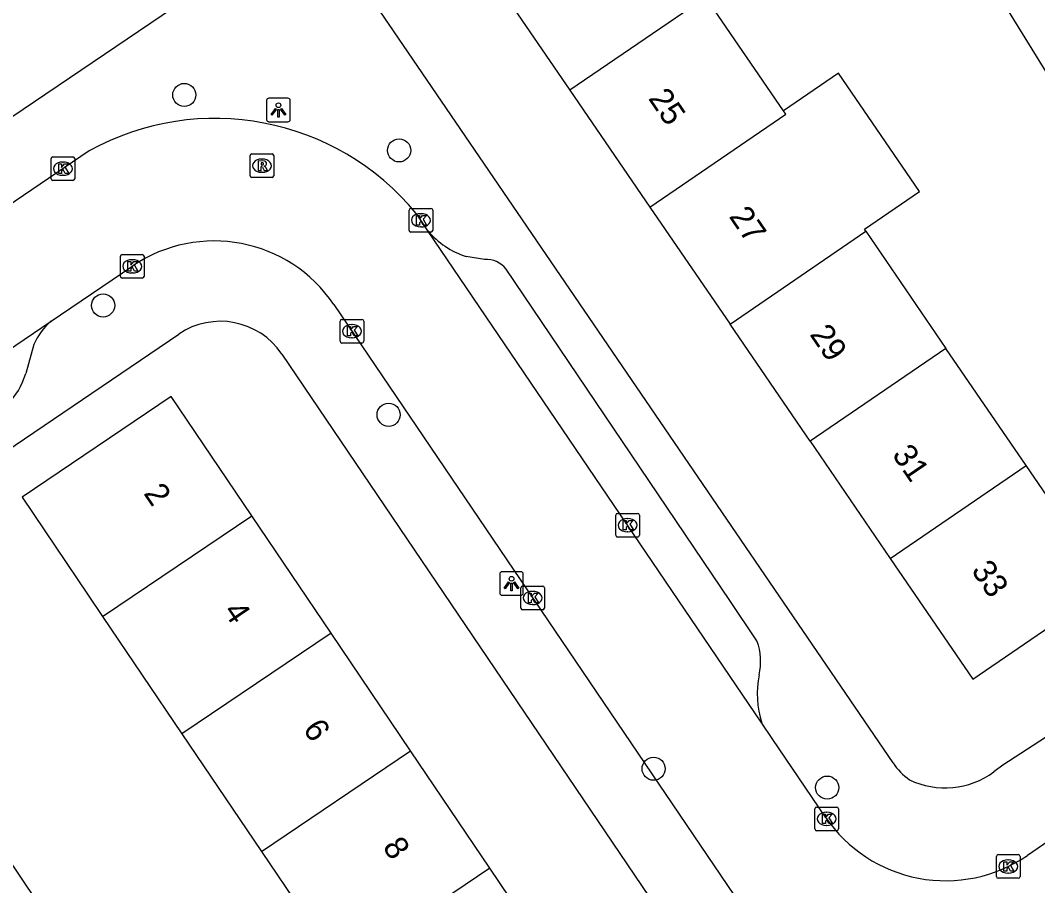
# Model space of a CAD drawing. Extents: x 160037 to 160839, y 385326 to 386441.
# Drawn here: x 160156.36 to 160199.4, y 386005.05 to 386041.67 of the extents above; entities that cross this region are included whole.
import ezdxf

# ---------------------------------------------------------------- set-up
doc = ezdxf.new("R2010")
doc.units = 0
for name, color, linetype in [('IMGEO_Boom', 7, 'Continuous'), ('IMGEO_Kolk', 7, 'Continuous'), ('IMGEO_Lichtpunt', 7, 'Continuous'), ('IMGEO_Pand', 7, 'Continuous'), ('IMGEO_Pand_nummerreeks', 7, 'Continuous'), ('IMGEO_Rijbaan_lokaal_open', 7, 'Continuous'), ('IMGEO_Rioolput', 7, 'Continuous'), ('IMGEO_Voetpad_open', 7, 'Continuous')]:
    doc.layers.add(name, color=color, linetype=linetype)

msp = doc.modelspace()

# ---------------------------------------------------------------- linework, layer by layer
at = {"layer": 'IMGEO_Boom'}
for centre in [(160163.294, 386038.508), (160172.383, 386036.165), (160159.86, 386029.602), (160171.938, 386024.977), (160183.15, 386010), (160190.492, 386009.202)]:
    msp.add_circle(centre, 0.489, dxfattribs=at)
at = {"layer": 'IMGEO_Kolk'}
for p, q in [((160157.657, 386034.965), (160157.657, 386035.817)), ((160157.732, 386035.891), (160158.584, 386035.891)), ((160158.658, 386035.817), (160158.658, 386034.965)), ((160158.145, 386035.671), (160158.17, 386035.671)), ((160158.168, 386035.111), (160158.143, 386035.111)), ((160158.584, 386034.891), (160157.732, 386034.891)), ((160172.8, 386032.78), (160172.8, 386033.632)), ((160172.875, 386033.706), (160173.727, 386033.706)), ((160173.801, 386033.632), (160173.801, 386032.78)), ((160173.288, 386033.486), (160173.313, 386033.486)), ((160173.311, 386032.926), (160173.286, 386032.926)), ((160173.727, 386032.706), (160172.875, 386032.706)), ((160160.589, 386030.832), (160160.589, 386031.684)), ((160160.664, 386031.758), (160161.516, 386031.758)), ((160161.077, 386031.538), (160161.102, 386031.538)), ((160161.59, 386031.684), (160161.59, 386030.832)), ((160161.516, 386030.758), (160160.664, 386030.758)), ((160161.1, 386030.978), (160161.075, 386030.978)), ((160169.883, 386028.088), (160169.883, 386028.94)), ((160169.958, 386029.014), (160170.81, 386029.014)), ((160170.884, 386028.94), (160170.884, 386028.088)), ((160170.371, 386028.794), (160170.396, 386028.794)), ((160170.394, 386028.234), (160170.369, 386028.234)), ((160170.81, 386028.014), (160169.958, 386028.014)), ((160181.546, 386019.879), (160181.546, 386020.731)), ((160181.621, 386020.805), (160182.473, 386020.805)), ((160182.547, 386020.731), (160182.547, 386019.879)), ((160182.034, 386020.585), (160182.059, 386020.585)), ((160182.057, 386020.025), (160182.032, 386020.025)), ((160182.473, 386019.805), (160181.621, 386019.805)), ((160177.604, 386017.727), (160178.456, 386017.727)), ((160177.529, 386016.801), (160177.529, 386017.653)), ((160178.017, 386017.507), (160178.042, 386017.507)), ((160178.53, 386017.653), (160178.53, 386016.801)), ((160178.04, 386016.947), (160178.015, 386016.947)), ((160178.456, 386016.727), (160177.604, 386016.727)), ((160189.97, 386007.453), (160189.97, 386008.305)), ((160190.045, 386008.379), (160190.897, 386008.379)), ((160190.971, 386008.305), (160190.971, 386007.453)), ((160190.458, 386008.159), (160190.483, 386008.159)), ((160190.897, 386007.379), (160190.045, 386007.379)), ((160190.481, 386007.599), (160190.456, 386007.599)), ((160197.649, 386005.44), (160197.649, 386006.292)), ((160197.724, 386006.366), (160198.576, 386006.366)), ((160198.137, 386006.146), (160198.162, 386006.146)), ((160198.65, 386006.292), (160198.65, 386005.44)), ((160198.576, 386005.366), (160197.724, 386005.366)), ((160198.16, 386005.586), (160198.135, 386005.586))]:
    msp.add_line(p, q, dxfattribs=at)
for points in [[(160157.657, 386034.965), (160157.657, 386035.817)], [(160157.732, 386035.891), (160158.584, 386035.891)], [(160158.658, 386035.817), (160158.658, 386034.965)], [(160157.978, 386035.591), (160158.101, 386035.591), (160158.101, 386035.44), (160158.231, 386035.591), (160158.395, 386035.591), (160158.249, 386035.44), (160158.402, 386035.191), (160158.25, 386035.191), (160158.165, 386035.355), (160158.101, 386035.288), (160158.101, 386035.191), (160157.978, 386035.191), (160157.978, 386035.591)], [(160158.584, 386034.891), (160157.732, 386034.891)], [(160172.8, 386032.78), (160172.8, 386033.632)], [(160172.875, 386033.706), (160173.727, 386033.706)], [(160173.801, 386033.632), (160173.801, 386032.78)], [(160173.121, 386033.406), (160173.244, 386033.406), (160173.244, 386033.255), (160173.374, 386033.406), (160173.538, 386033.406), (160173.392, 386033.255), (160173.545, 386033.006), (160173.393, 386033.006), (160173.308, 386033.17), (160173.244, 386033.103), (160173.244, 386033.006), (160173.121, 386033.006), (160173.121, 386033.406)], [(160173.727, 386032.706), (160172.875, 386032.706)], [(160160.589, 386030.832), (160160.589, 386031.684)], [(160160.664, 386031.758), (160161.516, 386031.758)], [(160161.59, 386031.684), (160161.59, 386030.832)], [(160160.91, 386031.458), (160161.033, 386031.458), (160161.033, 386031.307), (160161.163, 386031.458), (160161.327, 386031.458), (160161.181, 386031.307), (160161.334, 386031.058), (160161.182, 386031.058), (160161.097, 386031.222), (160161.033, 386031.155), (160161.033, 386031.058), (160160.91, 386031.058), (160160.91, 386031.458)], [(160161.516, 386030.758), (160160.664, 386030.758)], [(160169.883, 386028.088), (160169.883, 386028.94)], [(160169.958, 386029.014), (160170.81, 386029.014)], [(160170.884, 386028.94), (160170.884, 386028.088)], [(160170.204, 386028.714), (160170.327, 386028.714), (160170.327, 386028.563), (160170.457, 386028.714), (160170.621, 386028.714), (160170.475, 386028.563), (160170.628, 386028.314), (160170.476, 386028.314), (160170.391, 386028.478), (160170.327, 386028.411), (160170.327, 386028.314), (160170.204, 386028.314), (160170.204, 386028.714)], [(160170.81, 386028.014), (160169.958, 386028.014)], [(160181.546, 386019.879), (160181.546, 386020.731)], [(160181.621, 386020.805), (160182.473, 386020.805)], [(160182.547, 386020.731), (160182.547, 386019.879)], [(160181.867, 386020.505), (160181.99, 386020.505), (160181.99, 386020.354), (160182.12, 386020.505), (160182.284, 386020.505), (160182.138, 386020.354), (160182.291, 386020.105), (160182.139, 386020.105), (160182.054, 386020.269), (160181.99, 386020.202), (160181.99, 386020.105), (160181.867, 386020.105), (160181.867, 386020.505)], [(160182.473, 386019.805), (160181.621, 386019.805)], [(160177.604, 386017.727), (160178.456, 386017.727)], [(160177.529, 386016.801), (160177.529, 386017.653)], [(160177.85, 386017.427), (160177.973, 386017.427), (160177.973, 386017.276), (160178.103, 386017.427), (160178.267, 386017.427), (160178.121, 386017.276), (160178.274, 386017.027), (160178.122, 386017.027), (160178.037, 386017.191), (160177.973, 386017.124), (160177.973, 386017.027), (160177.85, 386017.027), (160177.85, 386017.427)], [(160178.53, 386017.653), (160178.53, 386016.801)], [(160178.456, 386016.727), (160177.604, 386016.727)], [(160189.97, 386007.453), (160189.97, 386008.305)], [(160190.045, 386008.379), (160190.897, 386008.379)], [(160190.971, 386008.305), (160190.971, 386007.453)], [(160190.291, 386008.079), (160190.414, 386008.079), (160190.414, 386007.928), (160190.544, 386008.079), (160190.708, 386008.079), (160190.562, 386007.928), (160190.715, 386007.679), (160190.563, 386007.679), (160190.478, 386007.843), (160190.414, 386007.776), (160190.414, 386007.679), (160190.291, 386007.679), (160190.291, 386008.079)], [(160190.897, 386007.379), (160190.045, 386007.379)], [(160197.649, 386005.44), (160197.649, 386006.292)], [(160197.724, 386006.366), (160198.576, 386006.366)], [(160198.65, 386006.292), (160198.65, 386005.44)], [(160197.97, 386006.066), (160198.093, 386006.066), (160198.093, 386005.915), (160198.223, 386006.066), (160198.387, 386006.066), (160198.241, 386005.915), (160198.394, 386005.666), (160198.242, 386005.666), (160198.157, 386005.83), (160198.093, 386005.763), (160198.093, 386005.666), (160197.97, 386005.666), (160197.97, 386006.066)], [(160198.576, 386005.366), (160197.724, 386005.366)]]:
    msp.add_lwpolyline(points, dxfattribs=at)
for centre, start, end in [((160157.734, 386035.815), 91.552, 178.448), ((160157.734, 386035.815), 91.552, 178.448), ((160158.582, 386035.815), 1.552, 88.448), ((160158.582, 386035.815), 1.552, 88.448), ((160157.734, 386034.967), 181.552, 268.448), ((160157.734, 386034.967), 181.552, 268.448), ((160158.582, 386034.967), 271.552, 358.448), ((160158.582, 386034.967), 271.552, 358.448), ((160172.877, 386033.63), 91.552, 178.448), ((160172.877, 386033.63), 91.552, 178.448), ((160173.725, 386033.63), 1.552, 88.448), ((160173.725, 386033.63), 1.552, 88.448), ((160172.877, 386032.782), 181.552, 268.448), ((160172.877, 386032.782), 181.552, 268.448), ((160173.725, 386032.782), 271.552, 358.448), ((160173.725, 386032.782), 271.552, 358.448), ((160160.666, 386031.682), 91.552, 178.448), ((160160.666, 386031.682), 91.552, 178.448), ((160161.514, 386031.682), 1.552, 88.448), ((160161.514, 386031.682), 1.552, 88.448), ((160160.666, 386030.834), 181.552, 268.448), ((160160.666, 386030.834), 181.552, 268.448), ((160161.514, 386030.834), 271.552, 358.448), ((160161.514, 386030.834), 271.552, 358.448), ((160169.96, 386028.938), 91.552, 178.448), ((160169.96, 386028.938), 91.552, 178.448), ((160170.808, 386028.938), 1.552, 88.448), ((160170.808, 386028.938), 1.552, 88.448), ((160169.96, 386028.09), 181.552, 268.448), ((160169.96, 386028.09), 181.552, 268.448), ((160170.808, 386028.09), 271.552, 358.448), ((160170.808, 386028.09), 271.552, 358.448), ((160181.623, 386020.729), 91.552, 178.448), ((160181.623, 386020.729), 91.552, 178.448), ((160182.471, 386020.729), 1.552, 88.448), ((160182.471, 386020.729), 1.552, 88.448), ((160181.623, 386019.881), 181.552, 268.448), ((160181.623, 386019.881), 181.552, 268.448), ((160182.471, 386019.881), 271.552, 358.448), ((160182.471, 386019.881), 271.552, 358.448), ((160177.606, 386017.651), 91.552, 178.448), ((160177.606, 386017.651), 91.552, 178.448), ((160178.454, 386017.651), 1.552, 88.448), ((160178.454, 386017.651), 1.552, 88.448), ((160177.606, 386016.803), 181.552, 268.448), ((160177.606, 386016.803), 181.552, 268.448), ((160178.454, 386016.803), 271.552, 358.448), ((160178.454, 386016.803), 271.552, 358.448), ((160190.047, 386008.303), 91.552, 178.448), ((160190.047, 386008.303), 91.552, 178.448), ((160190.895, 386008.303), 1.552, 88.448), ((160190.895, 386008.303), 1.552, 88.448), ((160190.047, 386007.455), 181.552, 268.448), ((160190.047, 386007.455), 181.552, 268.448), ((160190.895, 386007.455), 271.552, 358.448), ((160190.895, 386007.455), 271.552, 358.448), ((160197.726, 386006.29), 91.552, 178.448), ((160197.726, 386006.29), 91.552, 178.448), ((160198.574, 386006.29), 1.552, 88.448), ((160198.574, 386006.29), 1.552, 88.448), ((160197.726, 386005.442), 181.552, 268.448), ((160197.726, 386005.442), 181.552, 268.448), ((160198.574, 386005.442), 271.552, 358.448), ((160198.574, 386005.442), 271.552, 358.448)]:
    msp.add_arc(centre, 0.0765, start, end, dxfattribs=at)
for centre, major_axis, ratio, start_param, end_param in [((160158.144, 386035.391), (-0.387, 0.002), 0.722429, 4.712389, 7.853982), ((160158.169, 386035.391), (-0.39, 0.002), 0.717154, 1.570796, 4.712389), ((160173.287, 386033.206), (-0.387, 0.002), 0.722429, 4.712389, 7.853982), ((160173.312, 386033.206), (-0.39, 0.002), 0.717154, 1.570796, 4.712389), ((160161.076, 386031.258), (-0.387, 0.002), 0.722429, 4.712389, 7.853982), ((160161.101, 386031.258), (-0.39, 0.002), 0.717154, 1.570796, 4.712389), ((160170.37, 386028.514), (-0.387, 0.002), 0.722429, 4.712389, 7.853982), ((160170.395, 386028.514), (-0.39, 0.002), 0.717154, 1.570796, 4.712389), ((160182.033, 386020.305), (-0.387, 0.002), 0.722429, 4.712389, 7.853982), ((160182.058, 386020.305), (-0.39, 0.002), 0.717154, 1.570796, 4.712389), ((160178.016, 386017.227), (-0.387, 0.002), 0.722429, 4.712389, 7.853982), ((160178.041, 386017.227), (-0.39, 0.002), 0.717154, 1.570796, 4.712389), ((160190.457, 386007.879), (-0.387, 0.002), 0.722429, 4.712389, 7.853982), ((160190.482, 386007.879), (-0.39, 0.002), 0.717154, 1.570796, 4.712389), ((160198.136, 386005.866), (-0.387, 0.002), 0.722429, 4.712389, 7.853982), ((160198.161, 386005.866), (-0.39, 0.002), 0.717154, 1.570796, 4.712389)]:
    msp.add_ellipse(centre, major_axis=major_axis, ratio=ratio, start_param=start_param, end_param=end_param, dxfattribs=at)
at = {"layer": 'IMGEO_Lichtpunt'}
for p, q in [((160167.679, 386038.371), (160166.871, 386038.371)), ((160167.679, 386038.371), (160166.871, 386038.371)), ((160166.777, 386038.276), (160166.777, 386037.469)), ((160166.777, 386038.276), (160166.777, 386037.469)), ((160167.773, 386037.469), (160167.773, 386038.276)), ((160167.773, 386037.469), (160167.773, 386038.276)), ((160166.871, 386037.375), (160167.679, 386037.375)), ((160166.871, 386037.375), (160167.679, 386037.375)), ((160176.637, 386018.24), (160176.637, 386017.433)), ((160176.637, 386018.24), (160176.637, 386017.433)), ((160177.539, 386018.335), (160176.731, 386018.335)), ((160177.539, 386018.335), (160176.731, 386018.335)), ((160177.633, 386017.433), (160177.633, 386018.24)), ((160177.633, 386017.433), (160177.633, 386018.24)), ((160176.731, 386017.339), (160177.539, 386017.339)), ((160176.731, 386017.339), (160177.539, 386017.339))]:
    msp.add_line(p, q, dxfattribs=at)
for points in [[(160167.151, 386037.94), (160167.19, 386037.912), (160167.002, 386037.65), (160166.964, 386037.677), (160167.151, 386037.94)], [(160167.363, 386037.912), (160167.401, 386037.939), (160167.588, 386037.677), (160167.549, 386037.649), (160167.363, 386037.912)], [(160167.253, 386037.892), (160167.3, 386037.892), (160167.3, 386037.57), (160167.253, 386037.57), (160167.253, 386037.892)], [(160177.011, 386017.904), (160177.05, 386017.876), (160176.862, 386017.614), (160176.824, 386017.641), (160177.011, 386017.904)], [(160177.113, 386017.856), (160177.16, 386017.856), (160177.16, 386017.534), (160177.113, 386017.534), (160177.113, 386017.856)], [(160177.223, 386017.876), (160177.261, 386017.903), (160177.448, 386017.641), (160177.409, 386017.613), (160177.223, 386017.876)]]:
    msp.add_lwpolyline(points, dxfattribs=at)
for centre in [(160167.276, 386038.074), (160177.136, 386018.038)]:
    msp.add_circle(centre, 0.0994, dxfattribs=at)
for centre, start, end in [((160166.871, 386038.276), 90, 180), ((160166.871, 386038.276), 90, 180), ((160167.679, 386038.276), 0, 90), ((160167.679, 386038.276), 0, 90), ((160166.871, 386037.469), 180, 270), ((160166.871, 386037.469), 180, 270), ((160167.679, 386037.469), 270, 0), ((160167.679, 386037.469), 270, 360), ((160176.731, 386018.24), 90, 180), ((160176.731, 386018.24), 90, 180), ((160177.539, 386018.24), 0, 90), ((160177.539, 386018.24), 0, 90), ((160176.731, 386017.433), 180, 270), ((160176.731, 386017.433), 180, 270), ((160177.539, 386017.433), 270, 0), ((160177.539, 386017.433), 270, 360)]:
    msp.add_arc(centre, 0.0946, start, end, dxfattribs=at)
at = {"layer": 'IMGEO_Pand'}
for points in [[(160176.217, 386043.664), (160179.604, 386038.712)], [(160202.274, 386040.629), (160199.939, 386039.193), (160197.208, 386043.633)], [(160185.353, 386042.644), (160179.604, 386038.712)], [(160188.638, 386037.843), (160185.353, 386042.644)], [(160192.128, 386032.739), (160192.068, 386032.827), (160194.4, 386034.422), (160190.97, 386039.438), (160188.638, 386037.843)], [(160179.604, 386038.712), (160182.992, 386033.76)], [(160182.992, 386033.76), (160188.741, 386037.692), (160188.638, 386037.843)], [(160182.992, 386033.76), (160186.38, 386028.807)], [(160186.38, 386028.807), (160192.128, 386032.739)], [(160192.128, 386032.739), (160195.516, 386027.788)], [(160189.767, 386023.856), (160186.38, 386028.807)], [(160195.516, 386027.788), (160189.767, 386023.856)], [(160198.903, 386022.835), (160195.516, 386027.788)], [(160166.144, 386020.706), (160162.736, 386025.751), (160156.429, 386021.491), (160159.227, 386017.348), (160159.836, 386016.446)], [(160189.767, 386023.856), (160193.155, 386018.903)], [(160193.155, 386018.903), (160198.903, 386022.835)], [(160193.155, 386018.903), (160196.655, 386013.786), (160202.403, 386017.719), (160198.903, 386022.835)], [(160159.836, 386016.446), (160166.144, 386020.706)], [(160169.502, 386015.734), (160166.144, 386020.706)], [(160159.836, 386016.446), (160163.194, 386011.474)], [(160169.502, 386015.734), (160163.194, 386011.474)], [(160172.86, 386010.762), (160169.502, 386015.734)], [(160163.194, 386011.474), (160166.553, 386006.501)], [(160166.553, 386006.501), (160172.86, 386010.762)], [(160176.218, 386005.79), (160172.86, 386010.762)], [(160155.924, 386000.678), (160158.424, 386002.367), (160155.713, 386006.402)], [(160166.553, 386006.501), (160169.911, 386001.529)], [(160176.218, 386005.79), (160169.911, 386001.529)], [(160179.576, 386000.818), (160176.218, 386005.79)]]:
    msp.add_lwpolyline(points, dxfattribs=at)
at = {"layer": 'IMGEO_Rijbaan_lokaal_open'}
for points in [[(160159.266, 386036.142), (160139.533, 386022.738), (160124.669, 386012.596), (160120.145, 386009.569)], [(160173.603, 386032.759), (160173.237, 386033.299), (160173.106, 386033.492)], [(160187.724, 386011.929), (160173.603, 386032.759)], [(160157.666, 386028.94), (160158.051, 386029.201), (160161.116, 386031.277)], [(160169.622, 386029.641), (160186.862, 386004.189)], [(160128.204, 386009.022), (160129.232, 386009.733), (160151.628, 386024.852), (160157.666, 386028.94)], [(160190.421, 386007.951), (160188.166, 386011.277), (160187.724, 386011.929)], [(160202.396, 386008.684), (160198.96, 386006.332)]]:
    msp.add_lwpolyline(points, dxfattribs=at)
for centre, radius, start, end in [((160164.593, 386026.499), 11.017, 39.4041, 118.917), ((160164.551, 386026.204), 6.126, 34.1267, 124.0993), ((160195.497, 386011.394), 6.133, 214.1483, 304.38)]:
    msp.add_arc(centre, radius, start, end, dxfattribs=at)
at = {"layer": 'IMGEO_Rioolput'}
for p, q in [((160166.077, 386035.09), (160166.077, 386035.942)), ((160166.152, 386036.016), (160167.004, 386036.016)), ((160166.565, 386035.796), (160166.59, 386035.796)), ((160167.078, 386035.942), (160167.078, 386035.09)), ((160167.004, 386035.016), (160166.152, 386035.016)), ((160166.588, 386035.236), (160166.563, 386035.236))]:
    msp.add_line(p, q, dxfattribs=at)
for points in [[(160166.077, 386035.09), (160166.077, 386035.942)], [(160166.152, 386036.016), (160167.004, 386036.016)], [(160167.078, 386035.942), (160167.078, 386035.09)], [(160166.666, 386035.714), (160166.414, 386035.716), (160166.414, 386035.316)], [(160166.414, 386035.316), (160166.538, 386035.316), (160166.538, 386035.478), (160166.549, 386035.478)], [(160166.592, 386035.635), (160166.538, 386035.635), (160166.538, 386035.554)], [(160166.538, 386035.554), (160166.59, 386035.554)], [(160166.596, 386035.449), (160166.667, 386035.316), (160166.807, 386035.316), (160166.742, 386035.442)], [(160167.004, 386035.016), (160166.152, 386035.016)]]:
    msp.add_lwpolyline(points, dxfattribs=at)
for centre, radius, start, end in [((160166.154, 386035.94), 0.0765, 91.552, 178.448), ((160166.154, 386035.94), 0.0765, 91.552, 178.448), ((160167.002, 386035.94), 0.0765, 1.552, 88.448), ((160167.002, 386035.94), 0.0765, 1.552, 88.448), ((160166.548, 386035.425), 0.0533, 26.0293, 88.6989), ((160166.574, 386035.743), 0.19, 274.7715, 282.9687), ((160166.598, 386035.539), 0.0964, 77.0061, 93.1865), ((160166.612, 386035.596), 0.0378, 276.6634, 79.6772), ((160166.665, 386035.604), 0.109, 350.3612, 89.416), ((160166.663, 386035.604), 0.112, 277.5842, 350.9817), ((160166.647, 386035.389), 0.108, 29.5134, 73.7905), ((160166.154, 386035.092), 0.0765, 181.552, 268.448), ((160166.154, 386035.092), 0.0765, 181.552, 268.448), ((160167.002, 386035.092), 0.0765, 271.552, 358.448), ((160167.002, 386035.092), 0.0765, 271.552, 358.448)]:
    msp.add_arc(centre, radius, start, end, dxfattribs=at)
for centre, major_axis, ratio, start_param, end_param in [((160166.564, 386035.516), (-0.387, 0.002), 0.722429, 4.712389, 7.853982), ((160166.589, 386035.516), (-0.39, 0.002), 0.717154, 1.570796, 4.712389)]:
    msp.add_ellipse(centre, major_axis=major_axis, ratio=ratio, start_param=start_param, end_param=end_param, dxfattribs=at)
at = {"layer": 'IMGEO_Voetpad_open'}
for points in [[(160193.278, 386010.244), (160168.74, 386046.216), (160167.958, 386045.687)], [(160118.738, 386012.393), (160166.76, 386044.877)], [(160175.995, 386031.549), (160175.213, 386031.678)], [(160187.521, 386015.406), (160186.377, 386017.118), (160176.906, 386031.135)], [(160145.517, 386016.492), (160163.057, 386028.392)], [(160156.926, 386027.954), (160156.583, 386026.719)], [(160167.418, 386027.548), (160186.061, 386000), (160191.684, 385991.692)], [(160214.711, 386021.322), (160205.189, 386014.858), (160197.929, 386010.149), (160197.547, 386009.869)]]:
    msp.add_lwpolyline(points, dxfattribs=at)
for centre, radius, start, end in [((160176.286, 386035.016), 3.507, 220.0692, 252.1738), ((160176.073, 386030.511), 1.04, 36.8188, 94.3028), ((160159.306, 386026.939), 2.587, 129.3291, 156.8939), ((160164.815, 386025.789), 3.142, 34.0576, 124.0359), ((160153.748, 386027.535), 2.95, 313.802, 343.9373), ((160185.215, 386014.544), 2.462, 346.5069, 20.5018), ((160191.602, 386013.171), 4.072, 168.6951, 197.7579), ((160195.636, 386011.852), 2.854, 214.287, 234.2376), ((160195.482, 386012.665), 3.476, 244.1797, 306.4516)]:
    msp.add_arc(centre, radius, start, end, dxfattribs=at)

# ---------------------------------------------------------------- texts
at = {"layer": 'IMGEO_Pand_nummerreeks'}
for s, rotation, p in [('25', 304.3715, (160182.898, 386038.362)), ('27', 304.3715, (160186.313, 386033.369)), ('29', 304.3737, (160189.729, 386028.375)), ('31', 304.3737, (160193.209, 386023.288)), ('2', 304.0355, (160161.547, 386021.652)), ('33', 304.3737, (160196.561, 386018.388)), ('4', 304.0355, (160164.916, 386016.664)), ('6', 304.0355, (160168.284, 386011.677)), ('8', 304.0355, (160171.655, 386006.687))]:
    msp.add_text(s, height=1, rotation=rotation, dxfattribs=at).set_placement(p)

doc.saveas('drawing.dxf')
